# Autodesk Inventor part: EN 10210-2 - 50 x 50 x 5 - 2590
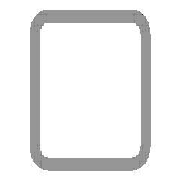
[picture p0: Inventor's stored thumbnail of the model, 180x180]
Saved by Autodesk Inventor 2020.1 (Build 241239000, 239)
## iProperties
Created: 2019-10
Part Number: EN 10210-2 - 50 x 50 x 5 - 2590
Material: Stahl, weich
Description: Rohrleitung
Document SubType Name: Modeling
Standard: DIN
Designer: lutzd
Standard Revision: 2006-07
Standards Organization: DIN
Language: de-DE
Size Designation: 50 x 50 x 5
Categories: <MemberInstance><Categories><Category DisplayName="Profile" InternalName="089c4875-fa83-4c05-b084-43b9cc11f5ed" Mnemonic="GRDR"><CategoryParameter DisplayName="
Stock Number: 50 x 50 x 5
Mass: 17753 g
Surface Area: 8785.64 cm^2
Volume: 2261.52 cm^3
Density: 7.85 g/cm^3
Appearance: Halbpoliert
IsCustomPart: 1
G_W: 50,000 mm
G_H: 50,000 mm
Dimensions: 50x50x2590 mm
Mass: 17,753 kg
DocNumber: ADSK-014208
Folder: .
+67A27D47-501C-4FED-B5A9-AB79F3B37B2D+SCHNITTDETAIL1: Schnittwinkel 90,00 grd
+1F734ECD-C7F1-4B81-A721-BCDD222EE388+SCHNITTDETAIL2: Schnittwinkel 90,00 grd
G_L: 2590,000 mm
_CCFamilyMember: 16
_CCFamilyDisplayName: DIN EN 10210-2 (USAS B17.1 quadratisch) - Rohrleitung — In Klammern angegebene Größen wurden aufgehoben
_FrameMemberDoc: Frame Member File
_Version: 15.0.0
_GetPNFromCC: 1
Title: Profil-Bauteil
Author: lutzd
Revision Number: -
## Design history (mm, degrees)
node "Startebene"
node "Endebene"
sketch "Skizze"
  geometry: L1 (-25, -17.5)-(-25, 17.5); L2 (-17.5, 25)-(17.5, 25); L3 (25, 17.5)-(25, -17.5); L4 (17.5, -25)-(-17.5, -25); L5 (-15, 20)-(15, 20); L6 (20, 15)-(20, -15); L7 (15, -20)-(-15, -20); L8 (-20, -15)-(-20, 15); L9 (0, 37.175)-(0, -37.175) reference; L10 (-37.175, 0)-(37.175, 0) reference; A1 r 7.5 centre (-17.5, -17.5) between (-25, -17.5) and (-17.5, -25); A2 r 7.5 centre (-17.5, 17.5) between (-17.5, 25) and (-25, 17.5); A3 r 7.5 centre (17.5, 17.5) between (25, 17.5) and (17.5, 25); A4 r 7.5 centre (17.5, -17.5) between (17.5, -25) and (25, -17.5); A5 r 5 centre (-15, -15) between (-20, -15) and (-15, -20); A6 r 5 centre (-15, 15) between (-15, 20) and (-20, 15); A7 r 5 centre (15, 15) between (20, 15) and (15, 20); A8 r 5 centre (15, -15) between (15, -20) and (20, -15)
  constraints: 16 end point, 16 point on circle, 16 tangent, 8 centre point, 6 equal radius, 4 parallel, 2 perpendicular, 2 other
  dimensions: "d7" = 7.5 radius of A1 (= G_IR); "d10" = 50 distance between parallel lines of L2 L4 (= G_H); "d11" = 50 distance between parallel lines of L1 L3 (= G_W); "d12" = 5 distance between parallel lines of L3 L6 (= G_T); "d15" = 25 distance between parallel lines of L2 L10 (= 0.5 x d10); "d16" = 25 distance between parallel lines of L9 L3 (= 0.5 x d11); "d19" = 5 radius of A5 (= G_T); "d20" = 5 distance between parallel lines of L4 L7 (= G_T)
extrude "Körper" new body sketch "Skizze" stored distance "d3" = 2590 (= G_L); taper "d4" = 0 deg
node "Driven Length"
  sketch "Sketch3"
    geometry: L1 (0, 0)-(10, 0) reference
    constraints: 2 end point, 1 horizontal
  workplane "Work Plane3"
  sketch "Sketch4"
    geometry: L1 (-2, 50)-(12, 50) reference; L2 (-2, 2640)-(12, 2640) reference
    dimensions: "d18" = 2590 distance between parallel lines of L1 L2 (derived)
workplane "Arbeitsebene4"
feature "Trennen1"
workplane "Arbeitsebene5"
feature "Trennen2"
body "Solid1"
other parameters: "G_W" = 50 [user parameter; used in 1 equation term], "G_H" = 50 [user parameter; used in 1 equation term], "G_T" = 5 [user parameter; used in 3 equation terms], "G_IR" = 7.5 [user parameter; used in 1 equation term], "G_L" = 2590 (= d18) [user parameter; used in 1 equation term], "d17" = 90 deg
